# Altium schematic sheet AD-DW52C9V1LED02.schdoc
size 127 x 101 mm
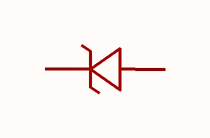
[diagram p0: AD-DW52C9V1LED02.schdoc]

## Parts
D?  ad-dw52c9v1led02  [WBFBP-02C_L1.0-W0.6-RD]  (value not drawn)

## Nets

Not connected (* = marked no-connect by the designer): D? 1(A) 2(C)

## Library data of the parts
D? = ad-dw52c9v1led02: 二极管配置:1个独立式;稳压值(标称值):9.1V;稳压值(范围值):8.5V~9.6V;耗散功率(Pd):100mW;; Manufacturer: CJ(江苏长电/长晶); AddInBom: yes; Diode Configuration: 1个独立式; Zener Voltage(Nom): 9.1V; Reverse Leakage Current (Ir): 500nA; Pd - Power Dissipation: 100mW; Impedance(Zzt): 15Ω; Impedance(Zzk): 100Ω; Operating Junction Temperature Range: -55℃~+150℃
